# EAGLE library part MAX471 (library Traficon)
High side current monitor
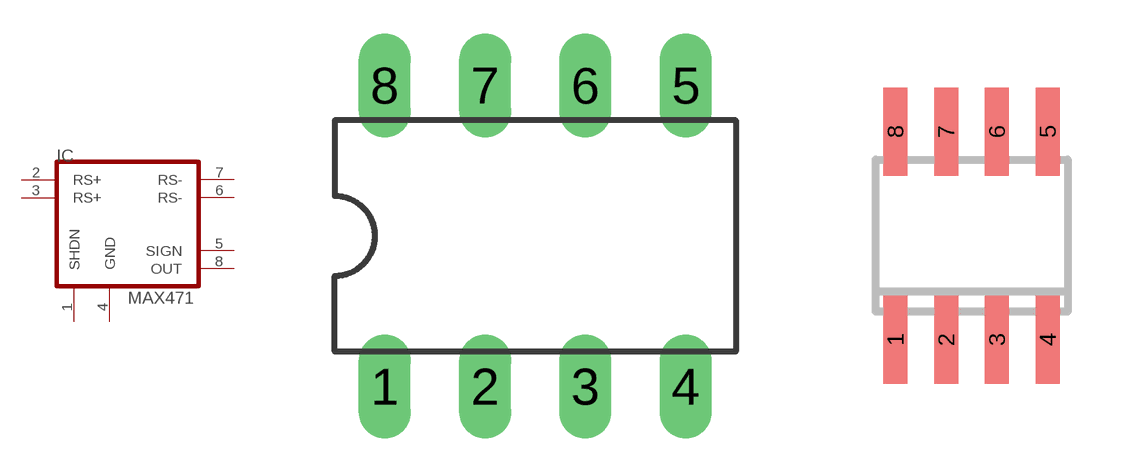
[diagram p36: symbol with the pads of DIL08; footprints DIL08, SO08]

Designator prefix IC

## MAX471CPA  [DIL08]
1  SHDN
2  RS+
3  RS+
4  GND
5  SIGN
6  RS-
7  RS-
8  OUT

## MAX471CSA  [SO08]
Pads as for DIL08

## Footprint DIL08 (pad centres in mm)
Dual In Line Package
drill 0.813 long: 1 -3.81,-3.81; 2 -1.27,-3.81; 3 1.27,-3.81; 4 3.81,-3.81; 5 3.81,3.81; 6 1.27,3.81; 7 -1.27,3.81; 8 -3.81,3.81

## Footprint SO08 (pad centres in mm)
Small Outline Package
smd 0.6 x 2.2: 1 -1.905,-2.6; 2 -0.635,-2.6; 3 0.635,-2.6; 4 1.905,-2.6; 5 1.905,2.6; 6 0.635,2.6; 7 -0.635,2.6; 8 -1.905,2.6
